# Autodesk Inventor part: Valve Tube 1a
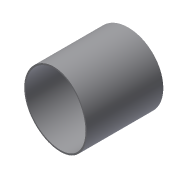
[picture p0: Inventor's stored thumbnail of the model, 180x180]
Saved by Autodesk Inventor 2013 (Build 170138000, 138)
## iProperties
Created: 2012-08
Part Number: Valve Tube 1a
Document SubType Name: Modeling
Designer: dms52
Density: 1 g/cm^3
Material: Generic
Author: dms52
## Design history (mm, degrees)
sketch "Sketch1"
  geometry: C1 r 38.1 at (0, 0); C2 r 36.449 at (0, 0); 1 further point
  constraints: 2 centre point, 2 coincident
  dimensions: "d0" = 76.2 diameter of C1; "d1" = 1.651 radial gap between concentric circles of C1 C2
extrude "Extrusion1" new body sketch "Sketch1" distance "d2" = 152.4; taper "d3" = 0 deg
sketch "Sketch3"
  geometry: L1 (-38.1, 0)-(38.1, 0) reference; L2 (0, -198.12)-(0, 1188.72) reference; C1 r 476.25 at (50.8, 551.18); 1 further point
  constraints: 1 centre point
  dimensions: "d7" = 551.18 distance from line of L1 C1.centre; "d8" = 952.5 diameter of C1; "d9" = 50.8 distance from line of C1.centre L2
extrude "Extrusion3" cut sketch "Sketch3" stored distance "d10" = 0; taper "d11" = 0 deg
body "Solid1"
